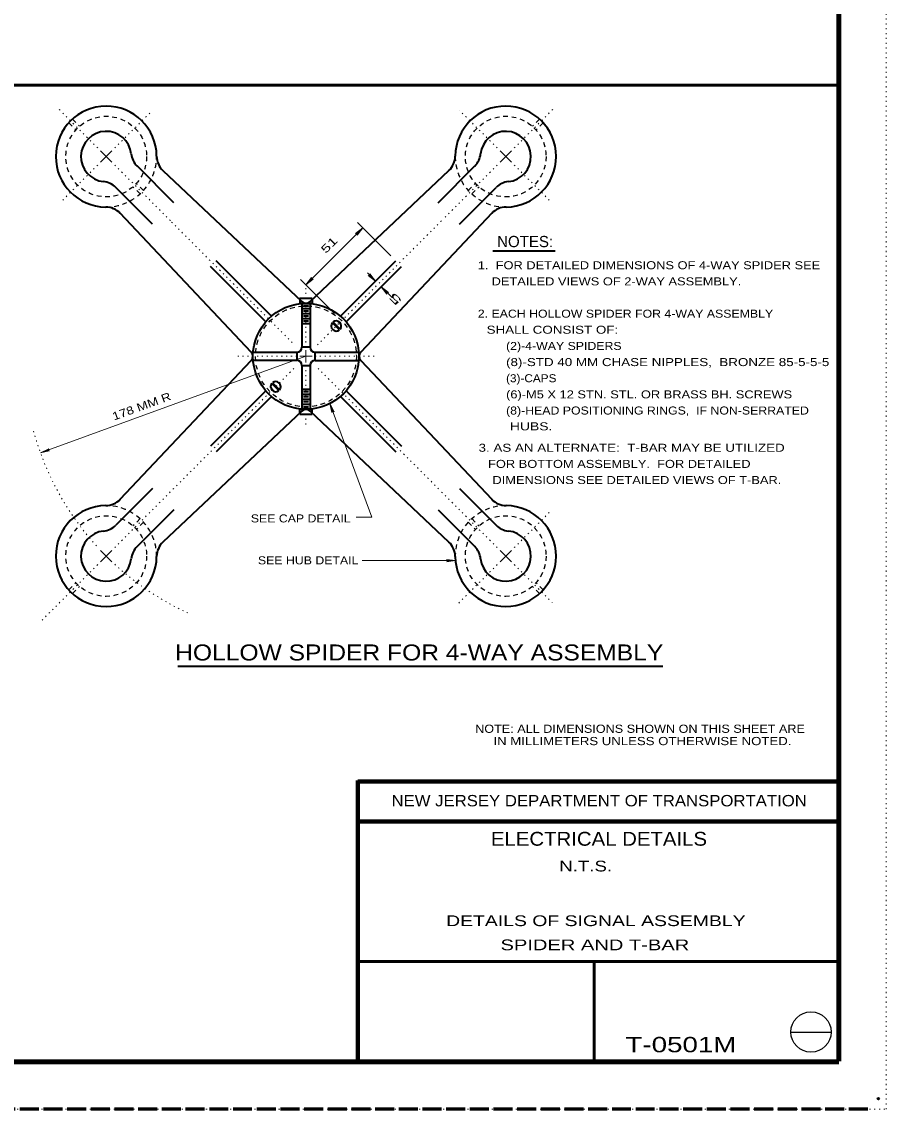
# Model space of a CAD drawing. Extents: x 312583 to 312854, y 144419 to 144597.
# Drawn here: x 312771.4 to 312853.5, y 144418.6 to 144521.9 of the extents above; entities that cross this region are included whole.
import ezdxf
from ezdxf.enums import TextEntityAlignment as Align

# ---------------------------------------------------------------- set-up
doc = ezdxf.new("R2010")
doc.units = 0
doc.header["$LTSCALE"] = 0.3
doc.header["$PDMODE"] = 32
doc.header["$PDSIZE"] = 0.15
for name, pattern in [('DOTTED', [1.5, 0.3, -1.2]), ('LONG_DASHED', [7.5, 6, -1.5]), ('SHORT_DASHED', [2.7, 1.5, -1.2])]:
    doc.linetypes.add(name, pattern=pattern)
for name, color, linetype, lineweight in [('1', 7, 'Continuous', 40), ('10', 7, 'Continuous', 25), ('2', 7, 'Continuous', 13), ('62', 7, 'DOTTED', 13), ('63', 7, 'LONG_DASHED', 60)]:
    doc.layers.add(name, color=color, linetype=linetype, lineweight=lineweight)
doc.layers.add('5', color=7, linetype='Continuous')

msp = doc.modelspace()

# ---------------------------------------------------------------- linework, layer by layer
at = {"layer": '1', "lineweight": 158}
for p, q in [((312849, 144423.1446), (312849, 144585.0846)), ((312616.5, 144423.0846), (312849, 144423.0846))]:
    msp.add_line(p, q, dxfattribs=at)
at = {"layer": '1', "lineweight": 53}
for p, q in [((312849.1073, 144515.8513), (312770.2547, 144515.8513)), ((312849, 144432.6066), (312803.2453, 144432.6066)), ((312825.7546, 144432.6066), (312825.7546, 144423.0846))]:
    msp.add_line(p, q, dxfattribs=at)
at = {"layer": '1', "linetype": 'SHORT_DASHED', "lineweight": 25}
for p, q in [((312775.8477, 144512.2869), (312776.5224, 144511.6046)), ((312776.1927, 144512.6243), (312776.8674, 144511.9496)), ((312820.5674, 144512.6319), (312819.885, 144511.9573)), ((312820.9047, 144512.2869), (312820.23, 144511.6123)), ((312782.6174, 144505.5249), (312781.935, 144506.1996)), ((312782.9547, 144505.8623), (312782.2724, 144506.5369)), ((312813.7977, 144505.8623), (312814.48, 144506.5446)), ((312814.135, 144505.5249), (312814.8174, 144506.2073)), ((312782.6174, 144474.6819), (312781.9427, 144473.9996)), ((312782.9547, 144474.3369), (312782.28, 144473.6623)), ((312813.7977, 144474.3446), (312814.48, 144473.6623)), ((312814.1427, 144474.6819), (312814.8174, 144473.9996)), ((312775.8554, 144467.9123), (312776.53, 144468.5869)), ((312776.1927, 144467.5749), (312776.875, 144468.2496)), ((312820.5674, 144467.5749), (312819.8927, 144468.2496)), ((312820.9047, 144467.9123), (312820.23, 144468.5946))]:
    msp.add_line(p, q, dxfattribs=at)
at = {"layer": '1'}
for p, q in [((312785.822, 144504.6893), (312782.3337, 144508.1776)), ((312810.9304, 144504.6893), (312814.4187, 144508.1776)), ((312784.7947, 144507.7483), (312797.9814, 144495.3129)), ((312798.771, 144495.3129), (312811.9577, 144507.7483)), ((312783.7904, 144502.6576), (312780.302, 144506.1459)), ((312812.9697, 144502.6576), (312816.4504, 144506.1459)), ((312793.1744, 144490.4983), (312780.7314, 144503.6849)), ((312816.021, 144503.6849), (312803.5857, 144490.4983)), ((312795.0987, 144493.9176), (312789.8394, 144499.1769)), ((312801.6537, 144493.9253), (312806.913, 144499.1769)), ((312794.5544, 144493.3809), (312789.3027, 144498.6326)), ((312802.198, 144493.3809), (312807.4574, 144498.6403)), ((312798.9704, 144495.6043), (312797.7744, 144495.6043)), ((312798.9704, 144495.1289), (312797.7744, 144495.1289)), ((312797.782, 144495.6119), (312797.782, 144495.1366)), ((312797.9967, 144495.1366), (312797.9967, 144490.9659)), ((312798.1347, 144494.8913), (312798.6254, 144494.8913)), ((312798.7634, 144495.1366), (312798.7634, 144490.9659)), ((312798.9704, 144495.6043), (312798.9704, 144495.1289)), ((312797.9967, 144494.6536), (312798.7634, 144494.6536)), ((312797.9967, 144494.1783), (312798.7634, 144494.1783)), ((312797.9967, 144493.6953), (312798.7634, 144493.6953)), ((312798.1347, 144494.4159), (312798.6254, 144494.4159)), ((312798.1347, 144493.9329), (312798.6254, 144493.9329)), ((312797.9967, 144493.2199), (312798.7634, 144493.2199)), ((312798.1347, 144493.4576), (312798.6254, 144493.4576)), ((312801.5694, 144492.6143), (312800.8947, 144493.2889)), ((312801.623, 144492.6679), (312800.9484, 144493.3426)), ((312798.7634, 144490.9659), (312797.9967, 144490.9659)), ((312780.7314, 144476.5219), (312793.1744, 144489.7086)), ((312793.3584, 144490.4906), (312797.5214, 144490.4906)), ((312793.3584, 144489.7239), (312797.5137, 144489.7239)), ((312797.5214, 144490.4906), (312797.5137, 144489.7239)), ((312799.2387, 144489.7163), (312799.2464, 144490.4829)), ((312799.2387, 144489.7163), (312803.394, 144489.7163)), ((312799.2464, 144490.4829), (312803.394, 144490.4829)), ((312803.5857, 144489.7086), (312816.021, 144476.5219)), ((312797.9967, 144489.2409), (312798.7634, 144489.2409)), ((312797.9967, 144489.2409), (312797.9967, 144485.0703)), ((312798.7634, 144489.2409), (312798.7634, 144485.0703)), ((312795.137, 144487.5313), (312795.8117, 144486.8566)), ((312795.1907, 144487.5849), (312795.8654, 144486.9103)), ((312794.562, 144486.8259), (312789.3027, 144481.5666)), ((312797.9967, 144486.9946), (312798.7634, 144486.9946)), ((312797.9967, 144486.5116), (312798.7634, 144486.5116)), ((312798.1347, 144486.7569), (312798.6254, 144486.7569)), ((312802.198, 144486.8259), (312807.4574, 144481.5666)), ((312795.0987, 144486.2816), (312789.847, 144481.0223)), ((312797.9967, 144486.0363), (312798.7634, 144486.0363)), ((312797.9967, 144485.5533), (312798.7634, 144485.5533)), ((312798.1347, 144486.2739), (312798.6254, 144486.2739)), ((312798.1347, 144485.7986), (312798.6254, 144485.7986)), ((312801.6537, 144486.2816), (312806.913, 144481.0223)), ((312797.9814, 144484.8939), (312784.7947, 144472.4586)), ((312797.782, 144484.5949), (312798.978, 144484.5949)), ((312798.1347, 144485.3156), (312798.6254, 144485.3156)), ((312811.9577, 144472.4586), (312798.771, 144484.8939)), ((312798.978, 144484.5949), (312798.978, 144485.0779)), ((312783.7904, 144477.5493), (312780.302, 144474.0609)), ((312812.9697, 144477.5493), (312816.4504, 144474.0609)), ((312785.822, 144475.5099), (312782.3337, 144472.0293)), ((312810.9304, 144475.5099), (312814.4187, 144472.0293))]:
    msp.add_line(p, q, dxfattribs=at)
at = {"layer": '1', "lineweight": 80}
for p, q in [((312803.31, 144423.1446), (312803.31, 144449.8146)), ((312803.31, 144449.7246), (312849, 144449.7246)), ((312803.31, 144445.9146), (312849, 144445.9146))]:
    msp.add_line(p, q, dxfattribs=at)
at = {"layer": '1'}
msp.add_lwpolyline([(312797.782, 144484.5949), (312797.782, 144485.0779), (312798.978, 144485.0779)], dxfattribs=at)
at = {"layer": '1', "linetype": 'SHORT_DASHED', "lineweight": 25}
for centre, radius in [((312779.4012, 144509.0746), 3.8333), ((312817.3512, 144509.0746), 3.8333), ((312798.3762, 144490.0996), 4.7917), ((312779.4012, 144471.1246), 3.8333), ((312817.3512, 144471.1246), 3.8333)]:
    msp.add_circle(centre, radius, dxfattribs=at)
at = {"layer": '1'}
msp.add_circle((312798.3743, 144490.0996), 5.0312, dxfattribs=at)
for centre, radius, start, end in [((312779.4022, 144509.0736), 4.7917, 0.58331, 269.41669), ((312817.3502, 144509.0736), 4.7917, 270.58331, 179.41669), ((312779.4022, 144509.0736), 2.3958, 6.03954, 263.96046), ((312817.3502, 144509.0736), 2.3958, 276.03954, 173.96046), ((312783.6906, 144509.5287), 1.9167, 186.05756, 225), ((312813.0618, 144509.5287), 1.9167, 315, 353.94244), ((312786.1102, 144509.1411), 1.9167, 180.57624, 226.68173), ((312810.6422, 144509.1411), 1.9167, 313.31827, 359.42376), ((312778.9471, 144504.7852), 1.9167, 45, 83.94244), ((312817.8053, 144504.7852), 1.9167, 96.05756, 135), ((312779.3347, 144502.3656), 1.9167, 43.31827, 89.42376), ((312817.4177, 144502.3656), 1.9167, 90.57624, 136.68173), ((312798.3762, 144495.7272), 0.575, 226.67977, 313.32023), ((312801.255, 144492.9784), 0.4792, 139.54804, 310.45196), ((312801.255, 144492.9784), 0.4792, 319.54804, 130.45196), ((312797.5175, 144490.9659), 0.4792, 270, 0), ((312799.2425, 144490.9621), 0.4792, 180, 270), ((312792.7524, 144490.0996), 0.575, 316.67115, 43.32885), ((312797.5137, 144489.2409), 0.4792, 0, 90), ((312799.2387, 144489.2371), 0.4792, 90, 180), ((312804.0038, 144490.0996), 0.575, 136.67977, 223.32023), ((312795.4974, 144487.2208), 0.4792, 139.54804, 310.45196), ((312795.4974, 144487.2208), 0.4792, 319.54804, 130.45196), ((312798.3762, 144484.472), 0.575, 46.67977, 133.32023), ((312779.3347, 144477.8336), 1.9167, 270.57624, 316.68173), ((312817.4177, 144477.8336), 1.9167, 223.31827, 269.42376), ((312779.4022, 144471.1256), 4.7917, 90.58331, 359.41669), ((312817.3502, 144471.1256), 4.7917, 180.58331, 89.41669), ((312778.9471, 144475.414), 1.9167, 276.05756, 315), ((312817.8053, 144475.414), 1.9167, 225, 263.94244), ((312779.4022, 144471.1256), 2.3958, 96.03954, 353.96046), ((312817.3502, 144471.1256), 2.3958, 186.03954, 83.96046), ((312783.6906, 144470.6705), 1.9167, 135, 173.94244), ((312786.1102, 144471.0581), 1.9167, 133.31827, 179.42376), ((312810.6422, 144471.0581), 1.9167, 0.57624, 46.68173), ((312813.0618, 144470.6705), 1.9167, 6.05756, 45)]:
    msp.add_arc(centre, radius, start, end, dxfattribs=at)
at = {"layer": '1', "linetype": 'SHORT_DASHED', "lineweight": 25}
for centre, start, end in [((312779.4022, 144509.0736), 269.41669, 0.58331), ((312817.3502, 144509.0736), 179.41669, 270.58331), ((312779.4022, 144471.1256), 359.41669, 90.58331), ((312817.3502, 144471.1256), 89.41669, 180.58331)]:
    msp.add_arc(centre, 4.7917, start, end, dxfattribs=at)
at = {"layer": '1', "linetype": 'DOTTED', "lineweight": 13}
for start, end in [(195.39383, 222.57479), (227.40257, 245.78885)]:
    msp.add_arc((312798.3762, 144490.0996), 26.8347, start, end, dxfattribs=at)
at = {"layer": '1'}
msp.add_point((312852.75, 144419.5846), dxfattribs=at)
at = {"layer": '10'}
msp.add_line((312844.4383, 144425.9059), (312848.2793, 144425.9059), dxfattribs=at)
msp.add_circle((312846.3494, 144425.9205), 1.9159, dxfattribs=at)
at = {"layer": '2', "linetype": 'DOTTED'}
for p, q in [((312778.5924, 144509.8873), (312774.782, 144513.6976)), ((312780.2177, 144509.8873), (312783.66, 144513.3296)), ((312816.5424, 144509.8873), (312812.9544, 144513.4753)), ((312818.1677, 144509.8873), (312821.9704, 144513.6976)), ((312778.5924, 144508.2619), (312775.081, 144504.7506)), ((312780.2177, 144508.2619), (312785.5844, 144502.9029)), ((312816.5424, 144508.2619), (312811.4517, 144503.1713)), ((312818.1677, 144508.2619), (312821.6024, 144504.8273)), ((312799.461, 144491.1806), (312811.4517, 144503.1713)), ((312797.0767, 144491.4029), (312785.5767, 144502.8953)), ((312798.38, 144490.9659), (312798.38, 144496.7159)), ((312797.5137, 144490.0996), (312791.7637, 144490.0996)), ((312799.2387, 144490.0996), (312804.9887, 144490.0996)), ((312797.2224, 144488.9419), (312786.2054, 144477.9326)), ((312798.38, 144489.2409), (312798.38, 144483.4909)), ((312799.5224, 144488.9573), (312811.122, 144477.3653)), ((312780.2177, 144471.9373), (312786.2054, 144477.9326)), ((312816.5424, 144471.9373), (312811.1144, 144477.3653)), ((312818.1677, 144471.9373), (312821.5027, 144475.2723)), ((312778.5924, 144470.3119), (312773.1644, 144464.8916)), ((312816.5424, 144470.3119), (312812.755, 144466.5246)), ((312818.1677, 144470.3119), (312821.7634, 144466.7239))]:
    msp.add_line(p, q, dxfattribs=at)
at = {"layer": '2'}
for p, q in [((312779.405, 144509.0746), (312778.8607, 144509.6189)), ((312779.405, 144509.0746), (312779.9417, 144509.6189)), ((312817.355, 144509.0746), (312816.8107, 144509.6189)), ((312817.355, 144509.0746), (312817.8917, 144509.6189)), ((312779.405, 144509.0746), (312778.8607, 144508.5379)), ((312779.405, 144509.0746), (312779.9417, 144508.5379)), ((312817.355, 144509.0746), (312816.8107, 144508.5379)), ((312817.355, 144509.0746), (312817.8917, 144508.5379)), ((312798.3647, 144496.8846), (312803.785, 144502.3049)), ((312803.785, 144502.3049), (312803.095, 144501.7683)), ((312803.785, 144502.3049), (312803.2484, 144501.6149)), ((312806.453, 144499.6446), (312803.2714, 144502.8263)), ((312803.095, 144501.7683), (312803.3634, 144501.8909)), ((312803.2484, 144501.6149), (312803.3634, 144501.8909)), ((312804.9887, 144497.2526), (312804.2144, 144498.0269)), ((312804.2987, 144497.7893), (312804.567, 144497.6743)), ((312804.9887, 144497.2526), (312804.2987, 144497.7893)), ((312804.4444, 144497.9426), (312804.567, 144497.6743)), ((312804.9887, 144497.2526), (312804.4444, 144497.9426)), ((312801.0864, 144494.1629), (312797.851, 144497.4059)), ((312798.3647, 144496.8846), (312798.9014, 144497.5746)), ((312798.3647, 144496.8846), (312799.0547, 144497.4213)), ((312798.9014, 144497.5746), (312798.7787, 144497.3063)), ((312799.0547, 144497.4213), (312798.7787, 144497.3063)), ((312806.5834, 144495.6503), (312805.5254, 144496.7083)), ((312805.5254, 144496.7083), (312806.062, 144496.0183)), ((312805.5254, 144496.7083), (312806.2154, 144496.1716)), ((312806.062, 144496.0183), (312805.947, 144496.2943)), ((312806.2154, 144496.1716), (312805.947, 144496.2943)), ((312798.38, 144490.0996), (312798.38, 144490.6746)), ((312798.38, 144490.0996), (312773.1644, 144480.9226)), ((312798.38, 144490.0996), (312797.805, 144490.0996)), ((312798.38, 144490.0996), (312798.955, 144490.0996)), ((312798.38, 144490.0996), (312798.38, 144489.5246)), ((312800.6494, 144485.6146), (312800.8487, 144484.7636)), ((312800.6494, 144485.6146), (312801.0557, 144484.8403)), ((312800.8487, 144484.7636), (312800.8564, 144485.0626)), ((312801.0557, 144484.8403), (312800.8564, 144485.0626)), ((312773.1644, 144480.9226), (312773.9387, 144481.3213)), ((312773.9387, 144481.3213), (312773.7164, 144481.1219)), ((312773.1644, 144480.9226), (312774.0154, 144481.1219)), ((312774.0154, 144481.1219), (312773.7164, 144481.1219)), ((312779.405, 144471.1246), (312778.8607, 144471.6689)), ((312779.405, 144471.1246), (312778.8607, 144470.5879)), ((312779.405, 144471.1246), (312779.9417, 144471.6689)), ((312779.405, 144471.1246), (312779.9417, 144470.5879)), ((312817.355, 144471.1246), (312816.8107, 144471.6689)), ((312817.355, 144471.1246), (312816.8107, 144470.5879)), ((312817.355, 144471.1246), (312817.8917, 144471.6689)), ((312817.355, 144471.1246), (312817.8917, 144470.5879)), ((312803.716, 144470.7029), (312812.5787, 144470.7029)), ((312811.7124, 144470.8103), (312811.9884, 144470.7029)), ((312812.5787, 144470.7029), (312811.7124, 144470.8103)), ((312811.7124, 144470.5956), (312811.9884, 144470.7029)), ((312812.5787, 144470.7029), (312811.7124, 144470.5956))]:
    msp.add_line(p, q, dxfattribs=at)
at = {"layer": '2', "lineweight": 40}
for p, q in [((312816.136, 144500.1236), (312822.047, 144500.1236)), ((312786.2009, 144460.6772), (312832.2764, 144460.6772))]:
    msp.add_line(p, q, dxfattribs=at)
at = {"layer": '2'}
msp.add_lwpolyline([(312800.6494, 144485.6146), (312804.636, 144474.8353), (312803.141, 144474.8353)], dxfattribs=at)
at = {"layer": '62'}
msp.add_lwpolyline([(312601.2, 144418.5846), (312853.5, 144418.5846), (312853.5, 144596.7846)], dxfattribs=at)
at = {"layer": '63'}
msp.add_line((312851.75, 144418.5846), (312583.526, 144418.5846), dxfattribs=at)

# ---------------------------------------------------------------- texts
at = {"layer": '1'}
for s, width, p in [('NOTE: ALL DIMENSIONS SHOWN ON THIS SHEET ARE', 1.15, (312814.4481, 144454.3374)), ('     IN MILLIMETERS UNLESS OTHERWISE NOTED.', 1.2, (312814.448, 144453.1674))]:
    msp.add_text(s, height=0.78, dxfattribs=dict(at, width=width)).set_placement(p)
at = {"layer": '1', "width": 1.1}
for s, height, p in [('NEW JERSEY DEPARTMENT OF TRANSPORTATION', 1.08, (312826.2285, 144447.3546)), ('ELECTRICAL DETAILS', 1.315, (312826.2107, 144443.6159))]:
    msp.add_text(s, height=height, dxfattribs=at).set_placement(p, align=Align.CENTER)
at = {"layer": '2'}
for s, rotation, width, p in [('51', 45, 1.5, (312800.2477, 144499.8088)), ('5', 135, 2.1, (312807.5468, 144495.3836)), ('178 MM R', 20, 1.25, (312780.1363, 144483.9944))]:
    msp.add_text(s, height=0.76, rotation=rotation, dxfattribs=dict(at, width=width)).set_placement(p)
msp.add_text('NOTES:', height=1.069, dxfattribs=at).set_placement((312816.5347, 144500.4686))
for s, width, p in [('1.  FOR DETAILED DIMENSIONS OF 4-WAY SPIDER SEE', 1.2, (312814.7024, 144498.3713)), ('  DETAILED VIEWS OF 2-WAY ASSEMBLY.', 1.2, (312815.3322, 144496.838)), ('2. EACH HOLLOW SPIDER FOR 4-WAY ASSEMBLY', 1.15, (312814.7024, 144493.7713)), ('   SHALL CONSIST OF:', 1.25, (312814.4813, 144492.2456)), ('(2)-4-WAY SPIDERS', 1.15, (312817.3857, 144490.7046)), ('(8)-STD 40 MM CHASE NIPPLES,  BRONZE 85-5-5-5', 1.25, (312817.3857, 144489.1713)), ('(3)-CAPS', 1.1, (312817.3857, 144487.638)), ('(6)-M5 X 12 STN. STL. OR BRASS BH. SCREWS', 1.2, (312817.3857, 144486.1046)), ('(8)-HEAD POSITIONING RINGS,  IF NON-SERRATED', 1.15, (312817.3857, 144484.5713)), ('    HUBS.', 1.3, (312816.2817, 144483.0686)), ('3. AS AN ALTERNATE:  T-BAR MAY BE UTILIZED', 1.25, (312814.7733, 144481.0351)), ('   FOR BOTTOM ASSEMBLY.  FOR DETAILED', 1.2, (312814.6578, 144479.5018)), ('  DIMENSIONS SEE DETAILED VIEWS OF T-BAR.', 1.2, (312815.4111, 144477.9684)), ('SEE CAP DETAIL', 1.15, (312793.1375, 144474.323)), ('SEE HUB DETAIL', 1.15, (312793.8142, 144470.3402))]:
    msp.add_text(s, height=0.76, dxfattribs=dict(at, width=width)).set_placement(p)
for s, height, width, p in [('HOLLOW SPIDER FOR 4-WAY ASSEMBLY', 1.52, 1.15, (312809.1348, 144461.21)), ('     N.T.S. ', 1.02, 1.3, (312823.9633, 144441.1717)), ('         DETAILS OF SIGNAL ASSEMBLY         ', 1.02, 1.35, (312825.9156, 144435.9799)), ('              SPIDER AND T-BAR              ', 1.02, 1.4, (312825.8237, 144433.6876))]:
    msp.add_text(s, height=height, dxfattribs=dict(at, width=width)).set_placement(p, align=Align.CENTER)
at = {"layer": '5', "width": 1.35}
msp.add_text('T-0501M   ', height=1.457, dxfattribs=at).set_placement((312835.0931, 144423.9969), align=Align.CENTER)

doc.saveas('drawing.dxf')
